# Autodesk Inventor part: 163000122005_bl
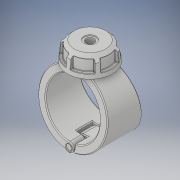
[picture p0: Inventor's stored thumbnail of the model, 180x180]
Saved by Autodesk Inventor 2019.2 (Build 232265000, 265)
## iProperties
Created: 2022-02
Part Number: 163000122005_bl
Material: Generic
Description: Plassadle Threaded 122x1/2''
Document SubType Name: Modeling
Designer: comp2
Density: 1 g/cm^3
Appearance: Default
Author: comp2
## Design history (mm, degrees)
derived "16300.ipt"
feature "Solid1::16300.ipt" dims "ScaleForDerivedMember" = 10
feature "Solid2::16300.ipt" dims "ScaleForDerivedMember" = 10
feature "Solid3::16300.ipt" dims "ScaleForDerivedMember" = 10
feature "Solid4::16300.ipt" dims "ScaleForDerivedMember" = 10
tag "TaggingFeature1"
body "Solid1"
body "Solid2"
body "Solid3"
body "Solid4"
other parameters: "d0" = 122 [user parameter], "d2" = 157 [user parameter], "d3" = 61 [user parameter], "d7" = 149.15 [user parameter], "d8" = 85 deg [user parameter], "d9" = 45 deg [user parameter], "d10" = 102 [user parameter], "d11" = 49 [user parameter], "d12" = 29.2495 [user parameter], "d13" = 42.84 [user parameter], "d14" = 27.9465 [user parameter], "d42" = 3.5 [user parameter], "d49" = 3.14 [user parameter], "d51" = 0 [user parameter], "d52" = 24.5 [user parameter], "d53" = 86.35 [user parameter], "d54" = 35 [user parameter], "d55" = 0 [user parameter], "d59" = 0 [user parameter], "d61" = 0 [user parameter], "d62" = 35 [user parameter], "d63" = 0 [user parameter], "d65" = 0 [user parameter], "d67" = 0 [user parameter], "d69" = 0 [user parameter], "d70" = 1 [user parameter], "d71" = 96 [user parameter], "d72" = 0 [user parameter], "d73" = 2 [user parameter], "d78" = 86.7 [user parameter], "d79" = 5.1 [user parameter], "d80" = 60 deg [user parameter], "d81" = 5.1 [user parameter], "d84" = 0 [user parameter], "d85" = 1 [user parameter], "d87" = 360 deg [user parameter], "d122" = 52 [user parameter], "d124" = 42.80128 [user parameter], "d125" = 2.08925 [user parameter], "d127" = 198 [user parameter], "d129" = 18.631 [user parameter], "d130" = 15.83635 [user parameter], "d131" = 33.8 [user parameter], "d132" = 45 deg [user parameter], "d133" = 23.66 [user parameter], "d134" = 9.3155 [user parameter], "d136" = 0 [user parameter], "d138" = 0 [user parameter], "d" = 122 [user parameter], "d1" = 25 [user parameter], "B" = 157 [user parameter], "E_" = 54 [user parameter], "E1" = 102 [user parameter], "H1" = 198 [user parameter], "H2" = 52 [user parameter], "H3" = 78 [user parameter], "H_costum" = 49 [user parameter], "Rp" = 18.631 [user parameter], "d128" = 41.785 [user parameter]
